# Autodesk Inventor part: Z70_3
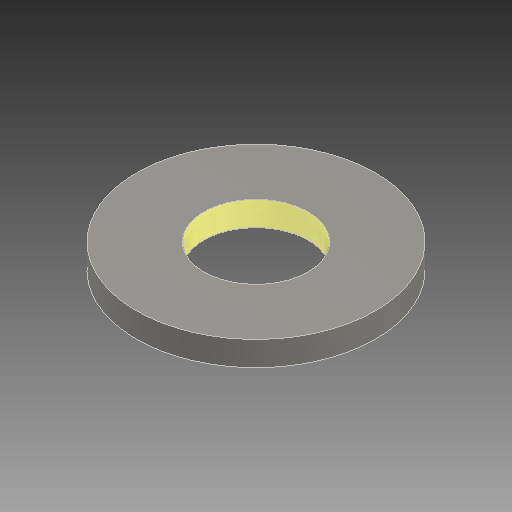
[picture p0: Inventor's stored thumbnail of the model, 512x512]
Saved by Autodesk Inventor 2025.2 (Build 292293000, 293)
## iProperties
Created: 2025-03
Part Number: Z70_3
Material: Všeobecné
Document SubType Name: Modeling
Designer: Patrik
Density: 1 g/cm^3
Appearance: Výchozí
Author: Patrik
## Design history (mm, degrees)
feature "Base1"
node "Těleso1"
